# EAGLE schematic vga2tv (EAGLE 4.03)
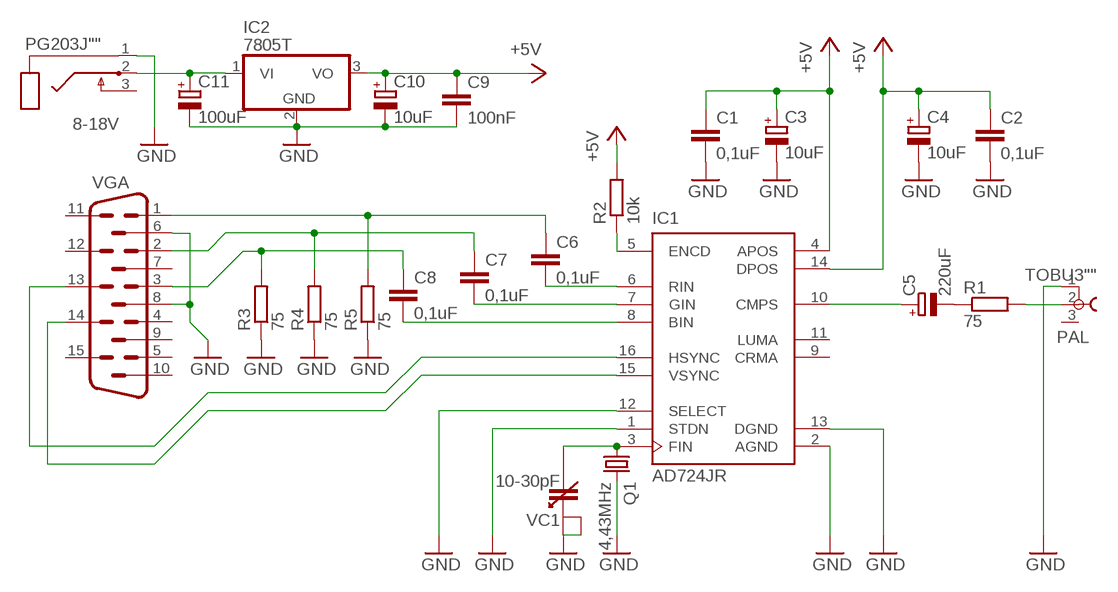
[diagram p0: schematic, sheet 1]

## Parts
8-18V  PG203J""  [PG203J]
C1  0,1uF  C-EU050-035X075  [C050-035X075]
C2  0,1uF  C-EU050-035X075  [C050-035X075]
C3  10uF  CPOL-EUTT2D5  [TT2D5]
C4  10uF  CPOL-EUTT2D5  [TT2D5]
C5  220uF  CPOL-EUE3.5-8  [E3,5-8]
C6  0,1uF  C-EU050-035X075  [C050-035X075]
C7  0,1uF  C-EU050-035X075  [C050-035X075]
C8  0,1uF  C-EU050-035X075  [C050-035X075]
C9  100nF  C-EU050-035X075  [C050-035X075]
C10  10uF  CPOL-EUTT2D5  [TT2D5]
C11  100uF  CPOL-EUTT2D6  [TT2D6]
IC1  AD724JR  [SO16W]
IC2  7805T  [TO220H]
PAL  TOBU3""  [TOBU3]
Q1  4,43MHz  HC49/S  [HC49/S]
R1  75  R-EU_0207/10  [0207/10]
R2  10k  R-EU_0207/10  [0207/10]
R3  75  R-EU_0207/10  [0207/10]
R4  75  R-EU_0207/10  [0207/10]
R5  75  R-EU_0207/10  [0207/10]
VC1  10-30pF  VARCAP""  [VARCAP1]
VGA  HM15H  [HDM15H]

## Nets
+5V: C1.2 C2.2 C3.+ C4.+ C9.2 C10.+ IC1.4(APOS) IC1.14(DPOS) IC2.3(VO) R2.2
BIN: C8.1 IC1.8(BIN)
BLU: C8.2 R3.2 VGA.3
CMPS: C5.+ IC1.10(CMPS)
FIN: IC1.3(FIN) Q1.1 VC1.1
GIN: C7.1 IC1.7(GIN)
GND: 8-18V.1 C1.1 C2.1 C3.- C4.- C9.1 C10.- C11.- IC1.1(STDN) IC1.2(AGND) IC1.12(SELECT) IC1.13(DGND) IC2.2(GND) PAL.1 Q1.2 R3.1 R4.1 R5.1 VC1.2 VGA.6 VGA.8
GRN: C7.2 R4.2 VGA.2
HSYNC: IC1.16(HSYNC) VGA.13
N$1: IC1.5(ENCD) R2.1
N$5: C5.- R1.1
RED: C6.2 R5.2 VGA.1
RIN: C6.1 IC1.6(RIN)
TVOUT: PAL.2 R1.2
VCC: 8-18V.2 C11.+ IC2.1(VI)
VSYNC: IC1.15(VSYNC) VGA.14
Unconnected: 8-18V.3 IC1.9(CRMA) IC1.11(LUMA) PAL.3 VC1.3 VGA.4 VGA.5 VGA.7 VGA.9 VGA.10 VGA.11 VGA.12 VGA.15

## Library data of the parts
8-18V = vga2tv:PG203J: MIC/HEADPHONE JACK KS-S stereo microphone/headphone jack PG203JN (Schukat)
C1 C2 C6-C9 = rcl:C-EU: CAPACITOR, European symbol
C3-C5 C10 C11 = rcl:CPOL-EU: POLARIZED CAPACITOR, European symbol
IC1 = vga2tv:AD724
IC2 = linear:78*: Positive VOLTAGE REGULATOR
PAL = vga2tv:TOBU3: Female Cinch CONNECTOR
Q1 = crystal:HC49/S: CRYSTAL
R1-R5 = rcl:R-EU_: RESISTOR, European symbol
VC1 = vga2tv:VARCAP
VGA = con-subd:HM15H: HARTING SUB-D

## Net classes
0 default: width 0.508 mm, drill 0.508 mm, clearance 0.381 mm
